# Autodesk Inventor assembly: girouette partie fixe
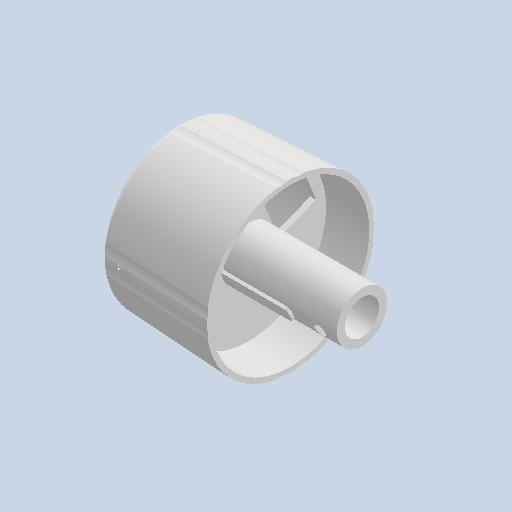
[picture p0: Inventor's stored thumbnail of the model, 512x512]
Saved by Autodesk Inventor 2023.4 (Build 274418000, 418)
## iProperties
Created: 2024-03
Part Number: girouette partie fixe
Document SubType Name: Assembly
Designer: mel
Author: mel
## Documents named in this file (3)
- D:\travail\année 2023-2024\IT\char à voile\girouette partie fixe.iam
- D:\travail\année 2023-2024\IT\char à voile\base girouette.ipt
- D:\travail\année 2023-2024\IT\char à voile\support d'axe.ipt
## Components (2 placed, 2 different names)
1. base girouette:1 — Placage:1
2. support d'axe:1 — Placage:1
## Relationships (1: Mate 1)
- Placage:1 [Mate]: base girouette:1 ↔ support d'axe:1
